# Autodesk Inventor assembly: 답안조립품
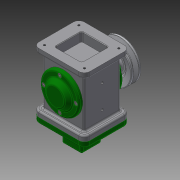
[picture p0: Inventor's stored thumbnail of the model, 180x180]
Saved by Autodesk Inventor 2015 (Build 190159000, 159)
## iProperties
Created: 2017-08
Part Number: 답안조립품
Document SubType Name: Assembly
Designer: owner
Author: owner
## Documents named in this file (18)
- C:\Users\owner\Desktop\470807V1012\답안조립품.iam
- C:\Users\owner\Desktop\470807V1012\본체1.ipt
- C:\Users\owner\Desktop\470807V1012\편심축.ipt
- C:\Users\owner\Desktop\470807V1012\베어링 17 x 40 x 12.ipt
- C:\Users\owner\Desktop\470807V1012\링크.ipt
- C:\Users\owner\Desktop\470807V1012\앞커버.ipt
- C:\Users\owner\Desktop\470807V1012\오일 실 17 30 8.ipt
- C:\Users\owner\Desktop\470807V1012\볼트 M4 x 8.ipt
- C:\Users\owner\Desktop\470807V1012\슬라이더.ipt
- C:\Users\owner\Desktop\470807V1012\클레비스 핀 6 x 22.ipt
- 클레비스 핀 6 x 22.ipt
- C:\Users\owner\Desktop\470807V1012\와셔 4x16.ipt
- C:\Users\owner\Desktop\470807V1012\E-링.ipt
- C:\Users\owner\Desktop\470807V1012\뒤커버.ipt
- C:\Users\owner\Desktop\470807V1012\키 4 x 4 x 12.ipt
- C:\Users\owner\Desktop\470807V1012\V-벨트풀리.ipt
- C:\Users\owner\Desktop\470807V1012\덮개.ipt
- C:\Users\owner\Desktop\470807V1012\볼트 M4 x 10.ipt
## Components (2 placed, 2 different names)
1. E-링:1
2. V-벨트풀리:1 — 각도:3
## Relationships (1: Angle 1)
- 각도:3 [Angle]: V-벨트풀리:1
